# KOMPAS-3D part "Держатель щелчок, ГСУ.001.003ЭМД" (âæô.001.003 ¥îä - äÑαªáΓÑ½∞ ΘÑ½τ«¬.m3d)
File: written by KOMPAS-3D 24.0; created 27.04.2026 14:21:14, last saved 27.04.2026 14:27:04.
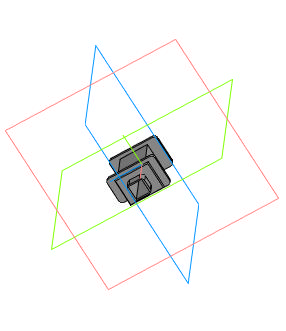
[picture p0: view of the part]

Document properties: Автор: USG_411; Полное имя файла: C:\Users\USG_411.STUD\Desktop\ГМ2704_411-23\Двигатель мясорубки\ГСУ.001.003 ЭМД - Держатель щелчок.m3d

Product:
- Part/product: Держатель щелчок  | designation ГСУ.001.003ЭМД
    Масса: 0.006405

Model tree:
1. Эскиз:1
2. Элемент выдавливания:1
     Расстояние 1 = 11
3. Эскиз:2  (with: Грань.Элемент выдавливания:1, Ребро.Элемент выдавливания:1)
4. Элемент выдавливания:2
     Расстояние 1 = 1
5. Массив по сетке:1  (with: Элемент выдавливания:2, Эскиз:2, Ребро.Элемент выдавливания:1)  (2 pattern instances)
     Шаг 1 = 12; Угол раствора = 90
6. Эскиз:4  (labels: Грань.Элемент выдавливания:2.Экземпляр ( 2, 1 ); Ребро.Элемент выдавливания:2.Экземпляр ( 2, 1 ))
7. Элемент выдавливания:3
     Расстояние 1 = 3.5
8. Эскиз:5  (with: Грань.Элемент выдавливания:2, Ребро.Элемент выдавливания:2)
9. Элемент выдавливания:4
     Расстояние 1 = 0.5; Угол 1 = 25
10. Эскиз:6  (with: Грань.Элемент выдавливания:4, Ребро.Элемент выдавливания:3)
11. Элемент выдавливания:5
     Расстояние 1 = 3
12. Эскиз:7  (with: Грань.Элемент выдавливания:3, Ребро.Элемент выдавливания:3)
13. Элемент выдавливания:6
     Расстояние 2 = 20
14. Скругление:1  (with: Ребро.Элемент выдавливания:6)
     Радиус = 0.2
15. Скругление:2  (with: Ребро.Элемент выдавливания:3)
     Радиус = 1
16. Скругление:3  (with: Ребро.Элемент выдавливания:5)
     Радиус = 1
17. Эскиз:8  (with: Грань.Элемент выдавливания:2, Ребро.Элемент выдавливания:2, Ребро.Элемент выдавливания:4)
18. Элемент выдавливания:7
19. Скругление:4  (with: Ребро.Элемент выдавливания:7, Ребро.Элемент выдавливания:2)  (labels: Ребро.Элемент выдавливания:2.Экземпляр ( 2, 1 ))
     Радиус = 1

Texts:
  ГСУ.001.003
  ГСУ.001.003 ЭМД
